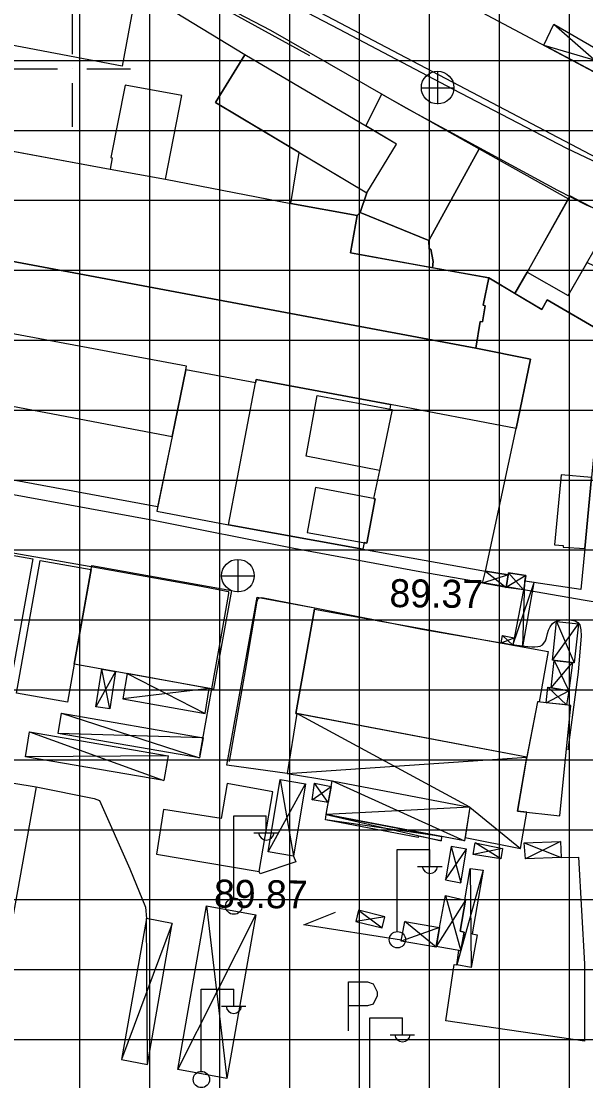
# Model space of a CAD drawing. Extents: x 417995 to 421451, y 4454518 to 4458015.
# Drawn here: x 419989.1 to 420110.2, y 4455282.9 to 4455510.2 of the extents above; entities that cross this region are included whole.
import ezdxf

# ---------------------------------------------------------------- set-up
doc = ezdxf.new("R2010")
doc.units = 0
for name, color, linetype in [('B_Betonzemin', 7, 'Continuous'), ('B_Imalat', 7, 'Continuous'), ('B_Sundurma', 7, 'Continuous'), ('B_Teras', 7, 'Continuous'), ('B_Ticari', 7, 'Continuous'), ('P_Grid', 7, 'Continuous'), ('S_Elektrik_Diregi', 7, 'Continuous'), ('S_Otopark', 7, 'Continuous'), ('S_Rogar_Kapagi', 7, 'Continuous'), ('Sinir_Cit_bir_taraf', 7, 'Continuous'), ('Sinir_Tel_bir_taraf', 7, 'Continuous'), ('TRFAT_TİCARET', 7, 'Continuous'), ('Y_Kot_Noktasi', 7, 'Continuous'), ('Y_Yol_Kotu', 7, 'Continuous'), ('Yol_Sose', 7, 'Continuous')]:
    doc.layers.add(name, color=color, linetype=linetype)

msp = doc.modelspace()

# ---------------------------------------------------------------- linework, layer by layer
at = {"layer": 'B_Betonzemin'}
for points in [[(419992.25, 4455345.95), (420004.72, 4455343.47), (420005.89, 4455343), (420012.39, 4455328.36)], [(420104.94, 4455330.81), (420108.66, 4455330.88), (420109.93, 4455307.97), (420109.9, 4455291.44), (420080.21, 4455295.78), (420081.93, 4455307.88), (420082.51, 4455307.8)], [(420012.39, 4455328.36), (420015.76, 4455320.12), (420015.93, 4455317.72)]]:
    msp.add_lwpolyline(points, dxfattribs=at)
at = {"layer": 'B_Imalat'}
for points in [[(420041.93, 4455518.07), (420118.28, 4455477.85), (420125.62, 4455492.07), (420049.45, 4455532.55)], [(419980.05, 4455460.02), (419984.53, 4455482.84), (420008.19, 4455478.45), (420020.02, 4455476.28), (420046.91, 4455471.08), (420061.13, 4455468.5), (420059.69, 4455460.48), (420089.37, 4455455.15), (420088.22, 4455449.31), (420088.62, 4455449.16), (420088.04, 4455445.69), (420087.55, 4455445.76), (420086.64, 4455440.04)], [(419977.25, 4455445.02), (419980.05, 4455460.02), (420086.64, 4455440.04), (420098.34, 4455437.73), (420095.27, 4455422.83), (420068.33, 4455427.99), (420039.5, 4455433.34), (420039.37, 4455432.63), (420024.4, 4455435.43), (420024.52, 4455436.19)], [(420024.4, 4455435.43), (420024.52, 4455436.19), (419977.25, 4455445.02), (419974.32, 4455430.06), (420021.45, 4455421.14)], [(420018.33, 4455406), (419971.46, 4455414.71), (419974.32, 4455430.06), (420021.45, 4455421.14)], [(419967.08, 4455399.19), (419991.54, 4455394.85), (419972.36, 4455288.24), (419947.98, 4455292.89)]]:
    msp.add_lwpolyline(points, close=True, dxfattribs=at)
at = {"layer": 'B_Sundurma'}
for p, q in [((420103.37, 4455509.59), (420119.53, 4455495.31)), ((420101.17, 4455505.07), (420121.39, 4455499.15)), ((420088.68, 4455392.21), (420093.13, 4455388.73)), ((420093.56, 4455391.46), (420088.04, 4455389.62)), ((420097.35, 4455391.3), (420093.13, 4455388.73)), ((420093.62, 4455391.86), (420096.87, 4455388.25)), ((420096.71, 4455376), (420097.16, 4455390.09)), ((420094.57, 4455376.38), (420099.13, 4455389.8)), ((420103.07, 4455373.14), (420108.64, 4455380.9)), ((420103.92, 4455381.41), (420107.69, 4455372.57)), ((420092.05, 4455376.84), (420094.87, 4455377.94)), ((420092.32, 4455378.41), (420094.57, 4455376.38)), ((420102.77, 4455367.21), (420107.36, 4455372.61)), ((420103.43, 4455373.09), (420106.56, 4455366.58)), ((420009.32, 4455370.71), (420005.05, 4455363.16)), ((420008.1, 4455362.71), (420006.4, 4455371.23)), ((420011.82, 4455370.25), (420028.53, 4455361.71)), ((420102.09, 4455367.32), (420106.07, 4455363.52)), ((420029.4, 4455367.08), (420010.9, 4455364.85)), ((420101.68, 4455364), (420106.56, 4455366.58)), ((419997.75, 4455361.76), (420027.29, 4455352.17)), ((420085.35, 4455341.63), (420048.24, 4455361.68)), ((419990.88, 4455357.78), (420019.69, 4455347.32)), ((420028.1, 4455356.51), (419997.01, 4455357.37)), ((420020.63, 4455352.6), (419990.02, 4455352.4)), ((420046.1, 4455348.84), (420097.57, 4455352.36)), ((420044.62, 4455347.52), (420047.51, 4455331.11)), ((420054.95, 4455342.57), (420052.02, 4455346.74)), ((420055.82, 4455347.23), (420084.18, 4455334.38)), ((420042.03, 4455332.01), (420050.05, 4455346.62)), ((420051.47, 4455343.18), (420055.59, 4455346.01)), ((420085.35, 4455341.63), (420054.48, 4455340.03)), ((420054.48, 4455340.03), (420079.16, 4455334.4)), ((420085.35, 4455341.63), (420096.21, 4455332.73)), ((420079.24, 4455335.32), (420054.33, 4455338.9)), ((420081.33, 4455333.15), (420083.39, 4455325.39)), ((420091.99, 4455330.5), (420086.5, 4455333.97)), ((420096.97, 4455333.95), (420104.94, 4455330.81)), ((420104.8, 4455334.23), (420097.25, 4455330.5)), ((420080.07, 4455326.01), (420084.64, 4455332.57)), ((420092.3, 4455332.76), (420086.07, 4455331.46)), ((420088.18, 4455328.08), (420082.51, 4455307.8)), ((420085.42, 4455328.48), (420085.62, 4455307.22)), ((420080.09, 4455322.64), (420083.4, 4455310.79)), ((420028.86, 4455320.43), (420033.22, 4455283.42)), ((420061.42, 4455319.49), (420066.49, 4455315.74)), ((420084.43, 4455321.68), (420078.1, 4455311.74)), ((420016.18, 4455286.44), (420015.93, 4455317.72)), ((420022.7, 4455285.32), (420039.39, 4455318.53)), ((420067.09, 4455318.11), (420060.89, 4455317.1)), ((420021.49, 4455316.66), (420010.59, 4455287.5)), ((420078.81, 4455315.77), (420070.62, 4455312.85)), ((420078.07, 4455311.58), (420071.35, 4455317.05))]:
    msp.add_line(p, q, dxfattribs=at)
for points in [[(420101.17, 4455505.07), (420103.37, 4455509.59), (420121.39, 4455499.15), (420119.53, 4455495.31)], [(420088.68, 4455392.21), (420093.56, 4455391.46), (420093.13, 4455388.73), (420088.04, 4455389.62)], [(420093.62, 4455391.86), (420097.35, 4455391.3), (420096.87, 4455388.25), (420093.13, 4455388.73)], [(420096.87, 4455388.25), (420094.57, 4455376.38), (420096.71, 4455376), (420099.13, 4455389.8), (420097.16, 4455390.09)], [(420103.07, 4455373.14), (420103.92, 4455381.41), (420108.64, 4455380.9), (420107.69, 4455372.57)], [(420092.05, 4455376.84), (420092.32, 4455378.41), (420094.87, 4455377.94), (420094.57, 4455376.38)], [(420102.77, 4455367.21), (420103.43, 4455373.09), (420107.36, 4455372.61), (420106.56, 4455366.58)], [(420009.32, 4455370.71), (420008.1, 4455362.71), (420005.05, 4455363.16), (420006.4, 4455371.23)], [(420029.4, 4455367.08), (420011.82, 4455370.25), (420010.9, 4455364.85), (420028.53, 4455361.71)], [(420101.68, 4455364), (420102.09, 4455367.32), (420106.56, 4455366.58), (420106.07, 4455363.52)], [(419997.75, 4455361.76), (420028.1, 4455356.51), (420027.29, 4455352.17), (419997.01, 4455357.37)], [(420046.1, 4455348.84), (420055.82, 4455347.23), (420085.35, 4455341.63), (420084.29, 4455335.07), (420096.21, 4455332.73), (420097.53, 4455340.51), (420095.52, 4455340.73), (420097.57, 4455352.36), (420048.24, 4455361.68)], [(419990.88, 4455357.78), (420020.63, 4455352.6), (420019.69, 4455347.32), (419990.02, 4455352.4)], [(420042.03, 4455332.01), (420044.62, 4455347.52), (420050.05, 4455346.62), (420047.51, 4455331.11)], [(420054.95, 4455342.57), (420051.47, 4455343.18), (420052.02, 4455346.74), (420055.59, 4455346.01)], [(420055.82, 4455347.23), (420085.35, 4455341.63), (420084.18, 4455334.38), (420054.48, 4455340.03)], [(420054.48, 4455340.03), (420079.24, 4455335.32), (420079.16, 4455334.4), (420074.24, 4455335.39), (420074.22, 4455335.13), (420054.33, 4455338.9)], [(420081.33, 4455333.15), (420080.07, 4455326.01), (420083.39, 4455325.39), (420084.64, 4455332.57)], [(420092.3, 4455332.76), (420091.99, 4455330.5), (420086.07, 4455331.46), (420086.5, 4455333.97)], [(420096.97, 4455333.95), (420104.8, 4455334.23), (420104.94, 4455330.81), (420097.25, 4455330.5)], [(420084.24, 4455321.72), (420085.42, 4455328.48), (420088.18, 4455328.08), (420085.86, 4455314.4), (420086.9, 4455314.19), (420085.62, 4455307.22), (420082.51, 4455307.8), (420082.98, 4455310.87), (420083.4, 4455310.79), (420084.12, 4455314.82), (420083.23, 4455314.98), (420084.43, 4455321.68)], [(420078.81, 4455315.77), (420080.09, 4455322.64), (420084.43, 4455321.68), (420083.23, 4455314.98), (420084.12, 4455314.82), (420083.4, 4455310.79), (420078.1, 4455311.74)], [(420022.7, 4455285.32), (420028.86, 4455320.43), (420039.39, 4455318.53), (420033.22, 4455283.42)], [(420067.09, 4455318.11), (420061.42, 4455319.49), (420060.89, 4455317.1), (420066.49, 4455315.74)], [(420016.18, 4455286.44), (420021.49, 4455316.66), (420015.93, 4455317.72), (420010.59, 4455287.5)], [(420078.81, 4455315.77), (420078.07, 4455311.58), (420070.62, 4455312.85), (420071.35, 4455317.05)]]:
    msp.add_lwpolyline(points, close=True, dxfattribs=at)
at = {"layer": 'B_Teras'}
for points in [[(420023.5, 4455494.22), (420011.34, 4455496.48), (420008.33, 4455480.95), (420008.61, 4455480.92), (420008.19, 4455478.45), (420020.02, 4455476.28)], [(420050.2, 4455416.92), (420052.58, 4455429.93), (420068.64, 4455426.87), (420065.97, 4455413.82)], [(420104.95, 4455412.91), (420103.52, 4455397.88), (420105.38, 4455397.75), (420105.38, 4455397.39), (420110, 4455397.08), (420111.45, 4455412.34)], [(420052.18, 4455410.15), (420050.44, 4455400.53), (420063.26, 4455398.24), (420065.02, 4455407.73)]]:
    msp.add_lwpolyline(points, close=True, dxfattribs=at)
at = {"layer": 'B_Ticari'}
for points in [[(420037.08, 4455502.95), (420020.43, 4455513.09), (420013.29, 4455514.42), (420010.74, 4455500.54), (419982.06, 4455506.01), (419977.97, 4455484.06), (420008.19, 4455478.45), (420020.02, 4455476.28), (420046.91, 4455471.08), (420048.74, 4455482.01), (420030.76, 4455492.74)], [(420037.08, 4455502.95), (420030.76, 4455492.74), (420063.23, 4455473.37), (420069.62, 4455483.83)], [(420063, 4455487.72), (420066.47, 4455494.53), (420087.36, 4455482.83), (420076.5, 4455463.15), (420061.78, 4455469.16), (420063.23, 4455473.37), (420069.62, 4455483.83)], [(420048.74, 4455482.01), (420063.23, 4455473.37), (420061.78, 4455469.16), (420061.13, 4455468.5), (420046.91, 4455471.08)], [(420087.36, 4455482.83), (420106.48, 4455472.11), (420097.62, 4455456.36), (420094.99, 4455451.78), (420089.37, 4455455.15), (420077.32, 4455457.32), (420077.46, 4455458.65), (420076.99, 4455461.33), (420076.59, 4455461.33), (420076.5, 4455463.15)], [(420097.62, 4455456.36), (420106.39, 4455451.36), (420115.97, 4455467.94), (420106.81, 4455472.7)], [(420061.13, 4455468.5), (420061.78, 4455469.16), (420076.5, 4455463.15), (420076.59, 4455461.33), (420076.99, 4455461.33), (420077.46, 4455458.65), (420077.32, 4455457.32), (420059.69, 4455460.48)], [(420110.49, 4455458.46), (420117.55, 4455455.05), (420116.09, 4455438.88), (420114.01, 4455438.97), (420114.4, 4455443.12), (420101.91, 4455450.4), (420100.74, 4455448.33), (420094.99, 4455451.78), (420097.62, 4455456.36), (420106.39, 4455451.36)], [(420086.64, 4455440.04), (420087.55, 4455445.76), (420088.04, 4455445.69), (420088.62, 4455449.16), (420088.22, 4455449.31), (420089.37, 4455455.15), (420100.74, 4455448.33), (420101.91, 4455450.4), (420114.4, 4455443.12), (420111.45, 4455412.34), (420110, 4455397.08), (420109.11, 4455388.29), (420097.16, 4455390.09), (420097.35, 4455391.3), (420093.62, 4455391.86), (420093.56, 4455391.46), (420088.68, 4455392.21), (420095.27, 4455422.83), (420098.34, 4455437.73)], [(420024.4, 4455435.43), (420018.14, 4455405.07), (420033.53, 4455402.18), (420039.37, 4455432.63)], [(420062.4, 4455396.97), (420033.53, 4455402.18), (420039.37, 4455432.63), (420039.5, 4455433.34), (420068.33, 4455427.99), (420068.15, 4455426.96), (420068.64, 4455426.87), (420065.97, 4455413.82), (420064.65, 4455407.8), (420065.02, 4455407.73), (420063.26, 4455398.24), (420062.62, 4455398.35), (420062.4, 4455396.97), (420033.53, 4455402.18)], [(420062.62, 4455398.35), (420062.4, 4455396.97), (420088.68, 4455392.21), (420095.27, 4455422.83), (420068.33, 4455427.99), (420068.15, 4455426.96), (420068.64, 4455426.87), (420065.97, 4455413.82), (420064.65, 4455407.8), (420065.02, 4455407.73), (420063.26, 4455398.24)], [(420000.46, 4455372.31), (419999.02, 4455364.13), (419988.03, 4455366.07), (419993.13, 4455394.52), (420004.05, 4455392.55)], [(420004.2, 4455393.43), (420034.22, 4455388.1), (420030.36, 4455366.9), (420000.46, 4455372.31)], [(420048.24, 4455361.68), (420046.1, 4455348.84), (420033.22, 4455350.59), (420039.72, 4455386.65), (420052.06, 4455384.38), (420051.98, 4455384.09), (420048.01, 4455361.72)], [(420097.57, 4455352.36), (420048.01, 4455361.72), (420051.98, 4455384.09), (420102.15, 4455375.01), (420100.17, 4455364.17), (420099.85, 4455364.2)], [(420099.85, 4455364.2), (420097.44, 4455351.66), (420095.52, 4455340.73), (420104.61, 4455339.75), (420107.02, 4455363.42)], [(419983.02, 4455347.49), (419992.25, 4455345.95), (419983.7, 4455298.55), (419974.53, 4455300.28)], [(420019.59, 4455341.13), (420018.08, 4455331.55), (420040.15, 4455327.82), (420043.08, 4455344.92), (420033.27, 4455346.65), (420031.99, 4455339.2)]]:
    msp.add_lwpolyline(points, close=True, dxfattribs=at)
at = {"layer": 'P_Grid'}
for p, q in [((420000, 4455512.5), (420000, 4455503.12)), ((419987.5, 4455500), (419996.88, 4455500)), ((420000, 4455500), (420000, 4455500)), ((420003.12, 4455500), (420012.5, 4455500)), ((420000, 4455496.88), (420000, 4455487.5))]:
    msp.add_line(p, q, dxfattribs=at)
at = {"layer": 'S_Elektrik_Diregi'}
for p, q in [((420034.66, 4455322.21), (420034.66, 4455339.71)), ((420034.66, 4455339.71), (420041.66, 4455339.71)), ((420041.66, 4455336.21), (420041.66, 4455339.71)), ((420039, 4455336.07), (420044.25, 4455336.07)), ((420069.77, 4455315.02), (420069.77, 4455332.52)), ((420069.77, 4455332.52), (420076.77, 4455332.52)), ((420076.77, 4455329.02), (420076.77, 4455332.52)), ((420074.11, 4455328.88), (420079.36, 4455328.88)), ((420027.68, 4455285.03), (420027.68, 4455302.53)), ((420027.68, 4455302.53), (420034.68, 4455302.53)), ((420034.68, 4455299.03), (420034.68, 4455302.53)), ((420032.02, 4455298.89), (420037.27, 4455298.89)), ((420063.87, 4455278.91), (420063.87, 4455296.41)), ((420063.87, 4455296.41), (420070.88, 4455296.41)), ((420070.88, 4455292.91), (420070.88, 4455296.41)), ((420068.22, 4455292.77), (420073.47, 4455292.77))]:
    msp.add_line(p, q, dxfattribs=at)
for centre in [(420034.69, 4455320.37), (420069.8, 4455313.18), (420027.72, 4455283.19)]:
    msp.add_circle(centre, 1.75, dxfattribs=at)
for centre in [(420041.66, 4455336.22), (420076.77, 4455329.03), (420034.68, 4455299.04), (420070.88, 4455292.92)]:
    msp.add_arc(centre, 1.66, 184.8384, 355.1464, dxfattribs=at)
at = {"layer": 'S_Otopark'}
for points in [[(420059.3, 4455304.15), (420063.4, 4455304.15)], [(420059.3, 4455293.65), (420059.3, 4455304.15)], [(420063.4, 4455304.15), (420064.62, 4455303.73), (420065.46, 4455302.02), (420065.46, 4455301.11), (420064.62, 4455299.32), (420063.4, 4455298.97)], [(420063.4, 4455298.97), (420059.3, 4455298.97)]]:
    msp.add_lwpolyline(points, dxfattribs=at)
at = {"layer": 'S_Rogar_Kapagi'}
for p, q in [((420078.48, 4455492.42), (420078.48, 4455499.42)), ((420074.91, 4455495.88), (420081.91, 4455495.88)), ((420035.62, 4455387.74), (420035.62, 4455394.74)), ((420032.05, 4455391.2), (420039.05, 4455391.2))]:
    msp.add_line(p, q, dxfattribs=at)
for centre in [(420078.42, 4455495.94), (420035.57, 4455391.26)]:
    msp.add_circle(centre, 3.5, dxfattribs=at)
at = {"layer": 'Sinir_Cit_bir_taraf'}
msp.add_lwpolyline([(419979.64, 4455539.38), (419994.4, 4455532.22), (420015.9, 4455521.53), (420028.93, 4455514.99), (420050.9, 4455502.8)], dxfattribs=at)
at = {"layer": 'Sinir_Tel_bir_taraf'}
for points in [[(420047.51, 4455331.11), (420047.98, 4455329.87), (420040.36, 4455327.32), (420040.15, 4455327.82)], [(420070.65, 4455313.05), (420049.73, 4455316.4), (420056.48, 4455319.06)]]:
    msp.add_lwpolyline(points, dxfattribs=at)
at = {"layer": 'TRFAT_TİCARET'}
for p, q in [((420076.68, 4455202.54), (420076.68, 4455803.79)), ((420061.68, 4455185.7), (420061.68, 4455772.5)), ((420046.68, 4455173.41), (420046.68, 4455741.21)), ((420031.68, 4455161.13), (420031.68, 4455713.07)), ((420016.68, 4455148.86), (420016.68, 4455685.9)), ((420001.68, 4455136.59), (420001.68, 4455658.72)), ((420091.68, 4455212.55), (420091.68, 4455591.43)), ((420106.68, 4455210.47), (420106.68, 4455591.43)), ((419811.18, 4455501.77), (420192.89, 4455501.77)), ((419812.07, 4455486.77), (420207.08, 4455486.77)), ((419812.97, 4455471.77), (420206.04, 4455471.77)), ((419813.87, 4455456.77), (420205, 4455456.77)), ((419814.76, 4455441.77), (420203.95, 4455441.77)), ((419815.66, 4455426.77), (420202.91, 4455426.77)), ((419817.03, 4455411.77), (420201.86, 4455411.77)), ((419818.02, 4455396.77), (420200.81, 4455396.77)), ((419817.48, 4455381.77), (420199.76, 4455381.77)), ((419817.12, 4455366.77), (420198.73, 4455366.77)), ((419816.76, 4455351.77), (420197.71, 4455351.77)), ((419816.4, 4455336.77), (420196.69, 4455336.77)), ((419816.04, 4455321.77), (420195.67, 4455321.77)), ((419815.68, 4455306.77), (420194.61, 4455306.77)), ((419815.37, 4455291.77), (420193.5, 4455291.77))]:
    msp.add_line(p, q, dxfattribs=at)
at = {"layer": 'Yol_Sose'}
for points in [[(420015.86, 4455522.19), (420042.53, 4455508.25), (420071.59, 4455491.6), (420104.17, 4455473.97), (420110.32, 4455470.82), (420112.63, 4455469.77), (420113.86, 4455469.25), (420114.73, 4455468.88), (420115.76, 4455468.6), (420117.13, 4455468.42), (420118.08, 4455468.37), (420119.14, 4455468.37), (420120.23, 4455468.46), (420121.35, 4455468.85), (420122.62, 4455469.4), (420123.81, 4455469.97), (420127.95, 4455472.25), (420149.79, 4455487.8), (420158.13, 4455495.12), (420166.66, 4455503.43), (420169.41, 4455506.44), (420170.18, 4455507.4), (420171.04, 4455508.56), (420172.39, 4455510.71)], [(420113.58, 4455385.38), (420110.05, 4455385.92), (420074.57, 4455392.1), (420047.57, 4455397.11), (420017.48, 4455403.1), (419972.13, 4455411.42), (419931.24, 4455419.63), (419896.9, 4455426.28), (419890.79, 4455427.6), (419889.84, 4455427.93), (419888.93, 4455428.5), (419888.32, 4455429.27), (419888.12, 4455430.22), (419890.1, 4455442.8), (419899.45, 4455494.27), (419901.75, 4455508.51), (419903.05, 4455516.09)], [(420162.39, 4455512.59), (420159.08, 4455509.72), (420143.08, 4455497.12), (420134.29, 4455490.53), (420124.82, 4455483.03), (420122.46, 4455481.21), (420120.94, 4455480.2), (420119.98, 4455479.72), (420118.98, 4455479.32), (420117.64, 4455479.18), (420116.77, 4455479.19), (420115.49, 4455479.24), (420113.9, 4455479.46), (420112.7, 4455479.81), (420111.55, 4455480.28), (420106.12, 4455482.9), (420081.68, 4455495.59), (420057.33, 4455508.38), (420041.82, 4455516.58)], [(419863.89, 4455327.44), (419868.11, 4455356.81), (419872.88, 4455386.21), (419877.55, 4455411.65), (419878.16, 4455414.6), (419878.43, 4455415.18), (419878.87, 4455415.72), (419879.57, 4455416.02), (419880.65, 4455416.03), (419892.05, 4455413.57), (419930.45, 4455406.23), (419969.21, 4455399.33), (420002.46, 4455393.52), (420027.65, 4455389.01), (420031.38, 4455388.31), (420033.46, 4455387.89), (420033.54, 4455387.79), (420033.58, 4455387.43), (420031.86, 4455377.71), (420027.29, 4455352.67)], [(420033.78, 4455351.41), (420037.16, 4455370.91), (420039.7, 4455385.78), (420039.83, 4455386.27), (420040.13, 4455386.54), (420040.68, 4455386.57), (420052.06, 4455384.34), (420075.02, 4455379.81), (420093.33, 4455376.62), (420096.47, 4455376.19), (420097.74, 4455376.04), (420098.62, 4455376), (420099.29, 4455375.99), (420099.91, 4455376.05), (420100.42, 4455376.17), (420100.89, 4455376.41), (420101.22, 4455376.79), (420101.53, 4455377.31), (420101.75, 4455377.96), (420101.97, 4455378.83), (420102.23, 4455379.55), (420102.54, 4455380.27), (420103.08, 4455381.01), (420103.53, 4455381.38), (420104.27, 4455381.63), (420105.14, 4455381.79), (420105.98, 4455381.83), (420106.8, 4455381.8), (420107.91, 4455381.54), (420108.51, 4455381.21), (420108.96, 4455380.69), (420109.17, 4455379.67), (420109.18, 4455378.32), (420108.57, 4455370.58), (420106.33, 4455353.92)]]:
    msp.add_lwpolyline(points, dxfattribs=at)

# ---------------------------------------------------------------- texts
at = {"layer": 'Y_Kot_Noktasi'}
msp.add_text('89.87', height=6, rotation=359.3381, dxfattribs=at).set_placement((420030.41, 4455320.08))
at = {"layer": 'Y_Yol_Kotu'}
msp.add_text('89.37', height=6, rotation=359.3381, dxfattribs=at).set_placement((420068.06, 4455384.53))

doc.saveas('drawing.dxf')
